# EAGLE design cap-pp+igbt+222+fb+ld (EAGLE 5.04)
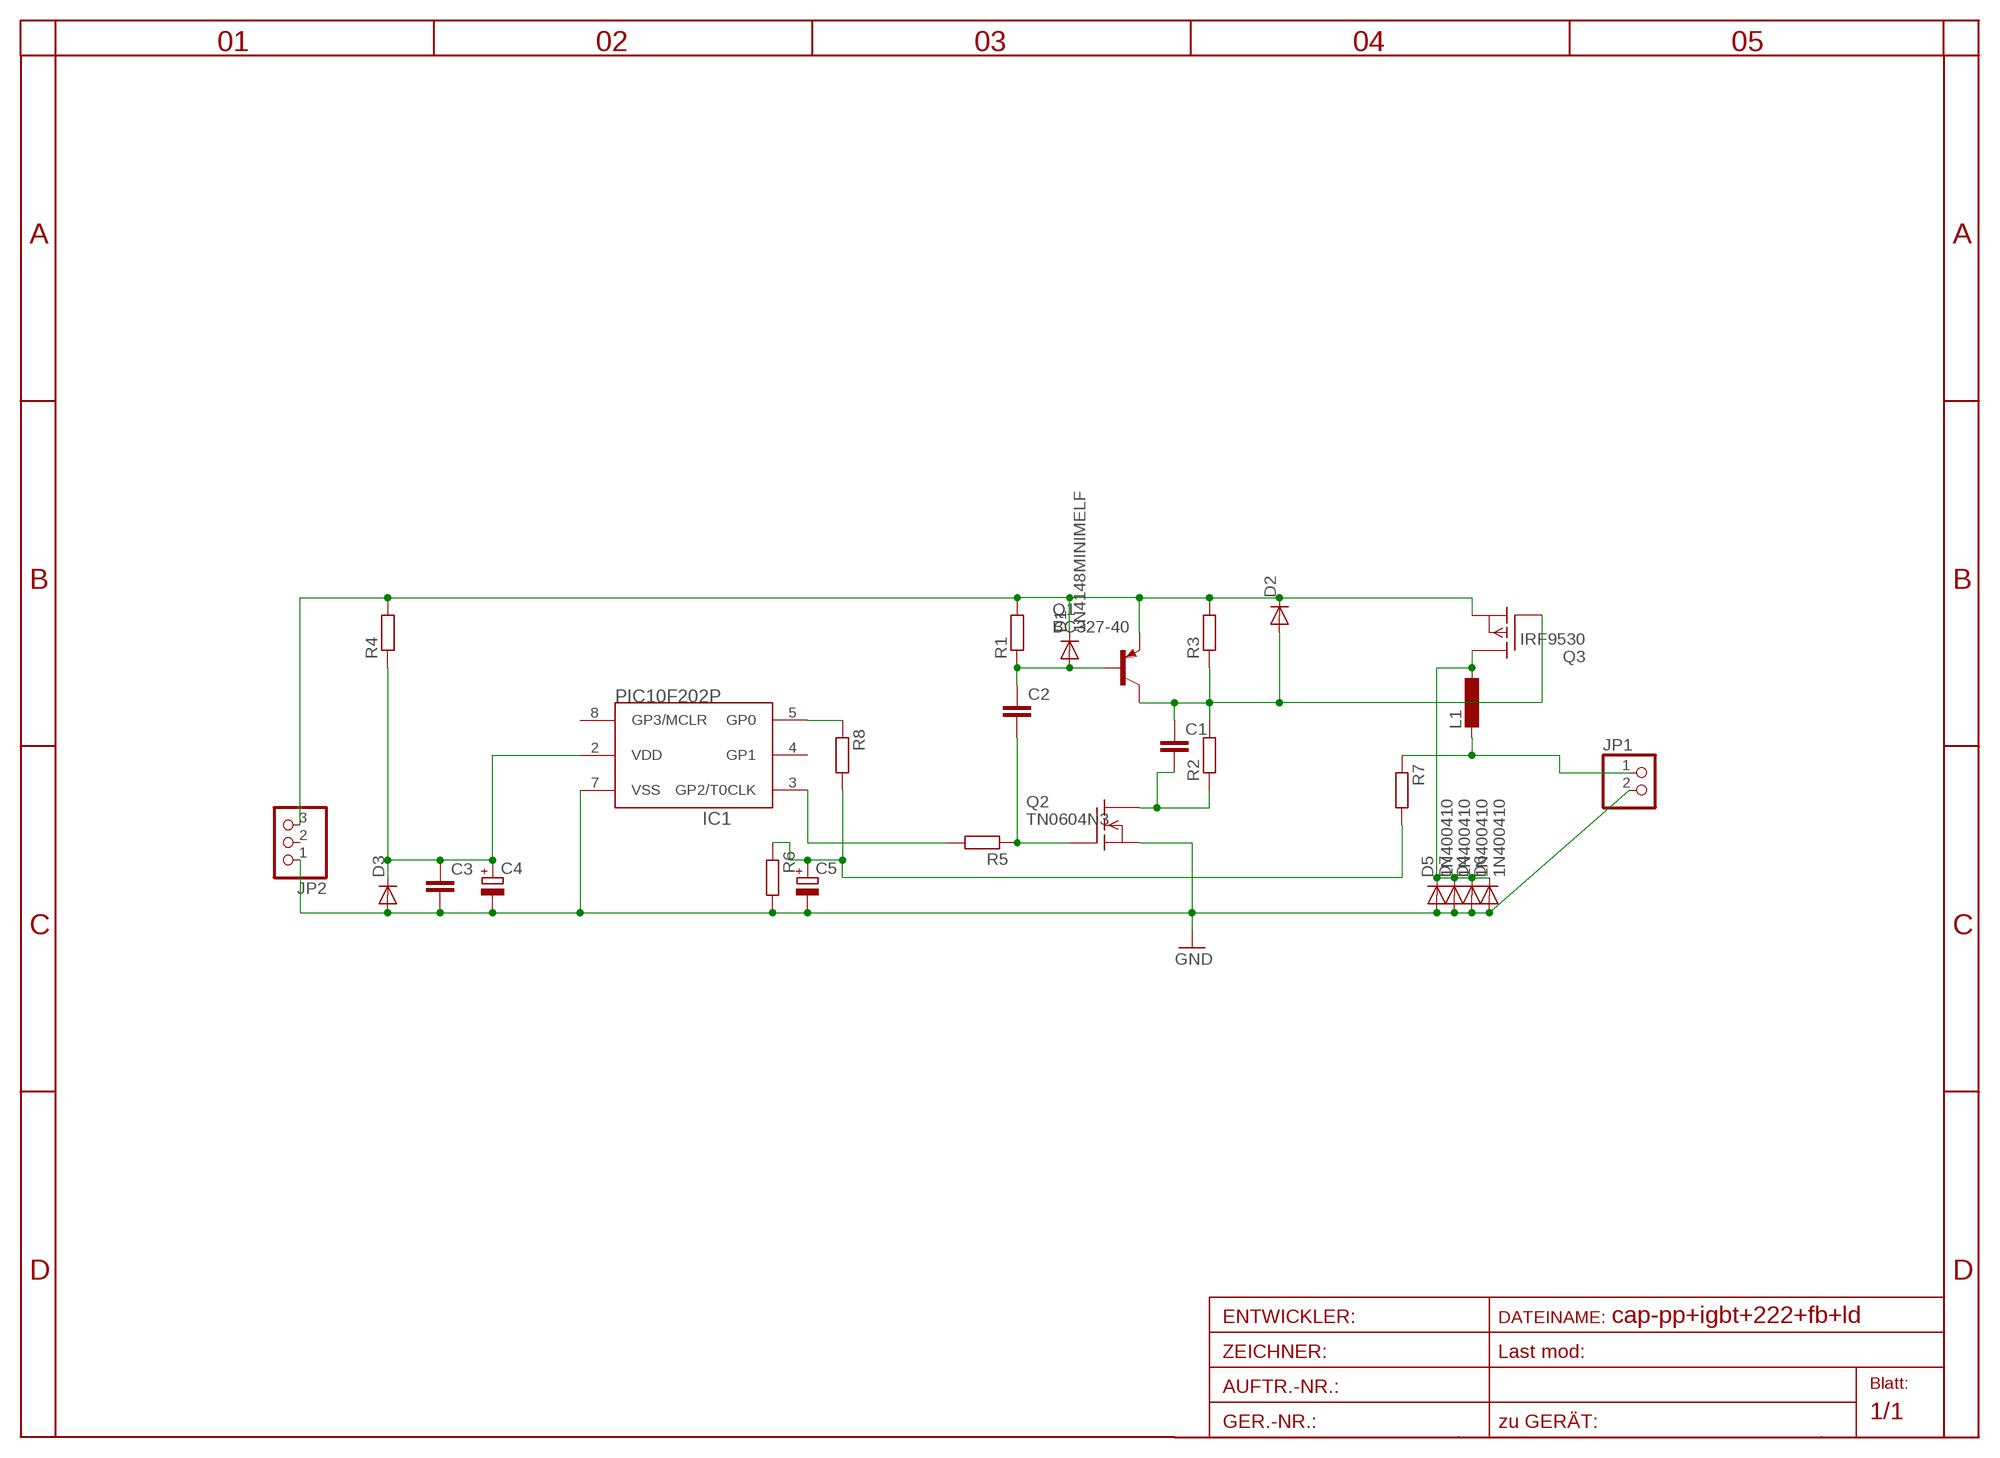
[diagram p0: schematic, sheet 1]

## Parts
C1  C-EU025_050-025X075  [C025_050-025X075]
C2  C-EU025_050-025X075  [C025_050-025X075]
C3  C-EU025_050-025X075  [C025_050-025X075]
C4  CPOL-EU5-13  [2,5-5-FLAT]
C5  CPOL-EU5-13  [2,5-5-FLAT]
D1  1N4148MINIMELF  [MINIMELF]
D2  DIODE-D-5  [D-5]
D3  DIODE-D-2.5  [D-2.5]
D4  1N400410  [DO41-10]
D5  1N400410  [DO41-10]
D6  1N400410  [DO41-10]
D7  1N400410  [DO41-10]
IC1  PIC10F202P  [DIL8]
JP1  PINHD-1X2  [1X02]
JP2  PINHD-1X3  [1X03]
L1  L-EU0204/7  [0204/7]
Q1  BC327-40  [TO92-EBC]
Q2  TN0604N3  [TO-92]
Q3  IRF9530  [TO220]
R1  R-EU_0204/2V  [0204V]
R2  R-EU_0204/2V  [0204V]
R3  R-EU_0204/2V  [0204V]
R4  R-EU_0204/2V  [0204V]
R5  R-EU_0204/2V  [0204V]
R6  R-EU_0204/2V  [0204V]
R7  R-EU_0204/2V  [0204V]
R8  R-EU_0204/2V  [0204V]

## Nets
BB: C2.2 Q2.2(G) R5.1
DRAIN: D4.C D5.C D6.C D7.C L1.1 Q3.2(D)
GND: C3.2 C4.- C5.- D3.A D4.A D5.A D6.A D7.A IC1.7(VSS) JP1.2 JP2.1 Q2.1(S) R6.2
MPOINT: C5.+ R6.1 R7.2 R8.2
N$1: C1.2 Q2.3(D) R2.1
N$3: IC1.3(GP2/T0CLK) R5.2
N$4: C3.1 C4.+ D3.C IC1.2(VDD) R4.1
N$5: IC1.5(GP0) R8.1
OUT: C1.1 D2.A Q1.C Q3.1(G) R2.2 R3.1
OUT+: JP1.1 L1.2 R7.1
TB: C2.1 D1.A Q1.B R1.1
V+: D1.C D2.C JP2.3 Q1.E Q3.3(S) R1.2 R3.2 R4.2
Unconnected: IC1.4(GP1) IC1.8(GP3/MCLR) JP2.2

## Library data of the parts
C1-C3 = rcl-2:C-EU: CAPACITOR, European symbol
C4 C5 = rcl-2:CPOL-EU: POLARIZED CAPACITOR, European symbol
D1 = diode-1:1N4148: DIODE
D2 D3 = diode-1:DIODE-: DIODE
D4-D7 = diode-1:1N4004: DIODE
IC1 = microchip-5:PIC10F20*: uPC nW 0,25/0,5k Program Flash memory
JP1 = pinhead:PINHD-1X2: PIN HEADER
JP2 = pinhead:PINHD-1X3: PIN HEADER
L1 = rcl-2:L-EU: INDUCTOR, European symbol
Q1 = transistor-pnp:BC327*: PNP Transistror
Q2 = transistor-fet:TN0604N3: N-Channel Enhancement MOSFET 40V; 4A; 0,75Ohm
Q3 = transistor-fet:IRF9530: P-Channel Enhancement MOSFET (HEXFET); -100V; -12A; 0,3Ohm
R1-R8 = rcl-2:R-EU_: RESISTOR, European symbol

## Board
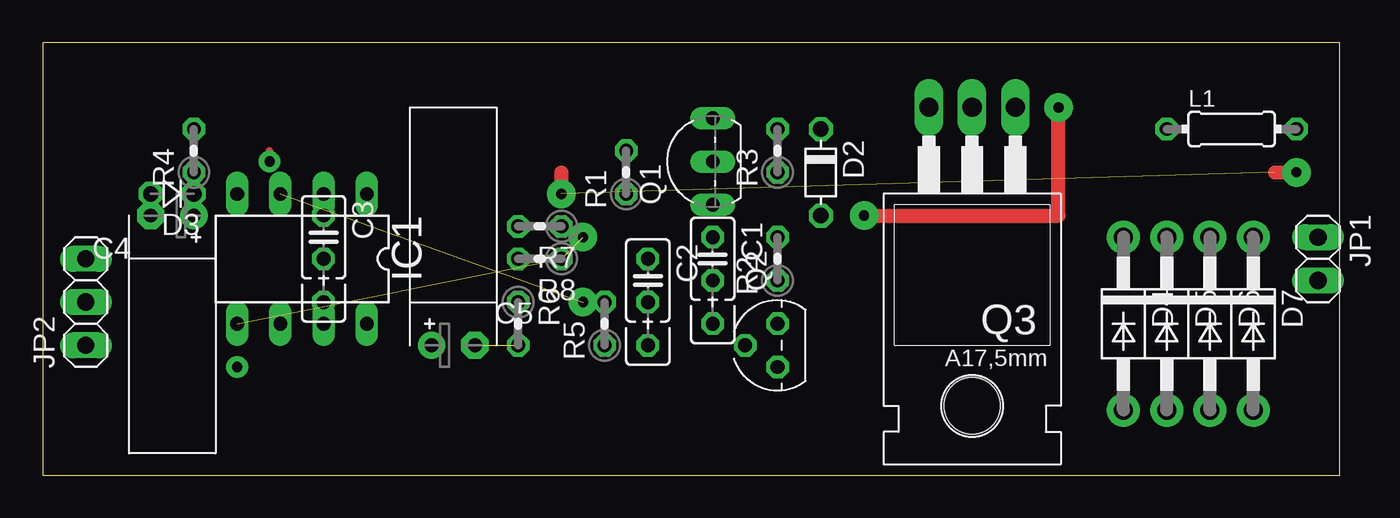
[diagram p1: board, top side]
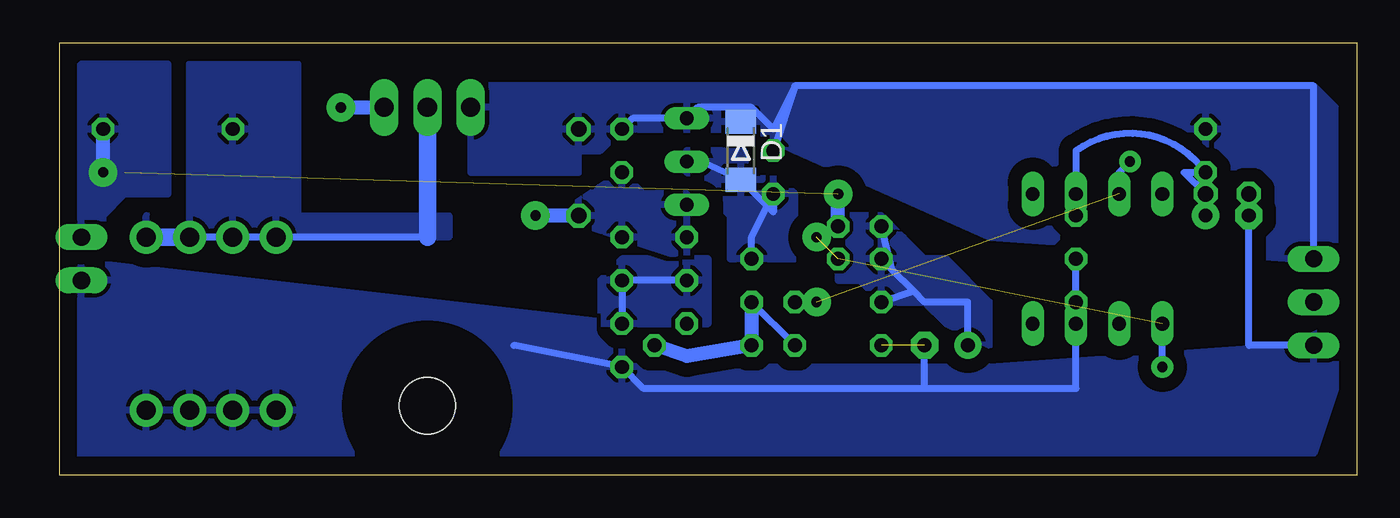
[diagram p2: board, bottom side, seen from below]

Size 76.2 x 25.4 mm. Coordinates in mm from the lower left corner, seen from the top.
Outline: 0,0 76.2,0 76.2,25.4 0,25.4 0,0
Copper layers (1*16): Top 0.035mm / dielectric 1.5mm / Bottom 0.035mm
Design rules "default": minimum track width 10mil, minimum drill 24mil, track to track 8mil, track to pad 8mil, pad to pad 8mil, via to via 8mil, smd to smd 8mil, copper to edge 40mil, drill to drill 8mil, minimum pad ring 10mil, minimum via ring 8mil, stop-mask expansion 4mil, vias tented up to drill 0mil, thermal gap 10mil

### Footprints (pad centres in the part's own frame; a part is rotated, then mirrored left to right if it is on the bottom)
C025_050-025X075 = drill 0.813 octagon: 1 -1.27,0; 2 1.27,0; 3 3.81,0
2,5-5-FLAT = drill 0.813 pad 1.6 round: + -1.27,0 | drill 0.813 pad 1.6 octagon: - 1.27,0
MINIMELF = smd 1.4 x 1.8: A 1.7,0; C -1.7,0
D-5 = drill 0.9 octagon: A 2.54,0; C -2.54,0
D-2.5 = drill 0.9 octagon: A 1.27,0; C -1.27,0
DO41-10 = drill 1.118 pad 1.93 round: A 5.08,0; C -5.08,0
DIL8 = drill 0.813 long: 1 -3.81,-3.81; 2 -1.27,-3.81; 3 1.27,-3.81; 4 3.81,-3.81; 5 3.81,3.81; 6 1.27,3.81; 7 -1.27,3.81; 8 -3.81,3.81
1X02 = drill 1.016 long: 1 -1.27,0; 2 1.27,0
1X03 = drill 1.016 long: 1 -2.54,0; 2 0,0; 3 2.54,0
0204/7 = drill 0.813 octagon: 1 -3.81,0; 2 3.81,0
TO92-EBC = drill 0.813 long: B 0,-1.27; C -2.54,-1.27; E 2.54,-1.27
TO-92 = drill 0.813 octagon: 1 -1.27,0; 2 0,1.905; 3 1.27,0
TO220 = drill 1.118 long: 1 -2.54,-6.35; 2 0,-6.35; 3 2.54,-6.35 | hole 3.302: 0,11.176
0204V = drill 0.813 octagon: 1 -1.27,0; 2 1.27,0

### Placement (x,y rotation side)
C1  39.37,12.7 270 top
C2  35.56,11.43 270 top
C3  16.51,13.97 270 top
C4  7.62,15.24 180 top
C5  24.13,7.62 0 top
D1  36.2,19.05 270 bottom
D2  45.72,17.78 270 top
D3  7.62,16.51 180 top
D4  63.5,8.89 270 top
D5  66.04,8.89 270 top
D6  68.58,8.89 270 top
D7  71.12,8.89 270 top
IC1  15.24,12.7 180 top
JP1  74.93,12.7 270 top
JP2  2.54,10.16 90 top
L1  69.85,20.32 0 top
Q1  38.1,18.41 90 top
Q2  43.18,7.62 90 top
Q3  54.61,15.24 180 top
R1  34.29,17.78 90 top
R2  43.18,12.7 90 top
R3  43.18,19.05 90 top
R4  8.89,19.05 90 top
R5  33.02,8.89 90 top
R6  27.94,8.89 270 top
R7  29.21,14.61 180 top
R8  29.21,12.7 180 top

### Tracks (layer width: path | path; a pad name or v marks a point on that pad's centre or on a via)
BB
  Bottom 0.406: R5.1 C2.2
  Bottom 0.813: Q2.2 39.37,6.99 35.56,7.62 C2.2
DRAIN
  Bottom 0.406: Q3.2 54.61,22.86 | 54.61,13.97 D4.C D5.C D6.C
  Bottom 1.016: 54.61,13.97 Q3.2 | D6.C D7.C
  pour Bottom (isolate 0.61): 68.58,24.13 62.23,24.13 62.23,15.24 55.88,15.24 53.34,15.24 53.34,13.97 71.12,13.97 71.12,15.24 68.58,15.24
GND  (1 unrouted)
  Bottom 0.406: 49.53,7.62 Q2.1 41.91,5.08 25.4,5.08 | D3.A C4.- 6.35,7.62 JP2.1 | C3.2 IC1.7 16.51,5.08 25.4,5.08 | 25.4,5.08 C5.-
  pour Bottom (isolate 0.813): 1.27,8.89 1.27,5.08 2.54,1.27 76.2,1.27 76.2,12.7 43.18,8.89 41.91,6.35 21.59,6.35 3.81,7.62
MPOINT
  Bottom 0.406: C5.+ 22.86,10.16 25.4,10.16 26.04,10.79 | 26.04,10.79 27.3,12.06 | 27.3,12.06 R7.2 | 26.04,10.79 R6.1 | 27.3,12.06 R8.2
  pour Bottom: 21.59,7.62 21.59,10.16 24.13,12.7 25.4,12.7 26.67,13.97 27.94,15.24 30.48,15.24 30.48,11.43 29.21,11.43 27.94,10.16 25.4,10.16 24.13,8.89
N$1
  Bottom 0.406: C1.2 R2.1 Q2.3
  pour Bottom (isolate 0.254, rank 3): 38.1,12.7 43.18,12.7 44.45,11.43 44.45,8.89 38.1,8.89
N$3  (via drill 0.6 pad 1.27, 0.6 pad 1.68)  (1 unrouted)
  Top 0.406: v13.34,18.41 13.34,19.05
  Bottom 0.406: IC1.3 13.97,17.78 v13.34,18.41
  Bottom 0.813: v31.75,10.16 R5.2
N$4
  Bottom 0.406: C4.+ D3.C 10.16,17.78 R4.1 arc-90 16.51,19.05 IC1.2 C3.1
N$5  (via drill 0.6 pad 1.27, 0.6 pad 1.68)  (2 unrouted)
  Bottom 0.406: v11.43,6.35 IC1.5
  other vias: 31.75,13.97
OUT  (via drill 0.6 pad 1.68)
  Top 0.813: v59.69,21.59 59.69,15.24 v48.26,15.24
  Bottom 0.813: v59.69,21.59 Q3.1 | D2.A v48.26,15.24
  pour Bottom (isolate 0.813, rank 2): 39.37,16.51 41.91,16.51 43.18,17.78 46.99,15.24 39.37,12.7
OUT+  (via drill 0.6 pad 1.68)  (1 unrouted)
  Top 0.813: v30.48,16.51 30.48,17.78 | 72.39,17.78 v73.66,17.78
  Bottom 0.813: R7.1 v30.48,16.51 | v73.66,17.78 L1.2
  pour Bottom (isolate 0.61): 69.85,24.13 74.93,24.13 76.2,22.86 76.2,13.97 73.66,13.97 73.66,15.24 72.39,16.51 69.85,16.51
TB
  Bottom 0.406: C2.1 35.56,13.97 R1.1 34.29,15.45 D1.A 38.94,18.62 39.16,18.62 Q1.B
  pour Bottom (isolate 0.813, rank 3): 36.83,12.7 33.02,12.7 33.02,16.51 35.56,19.05 39.37,19.05 39.37,17.78 36.83,15.24
V+
  Bottom 0.406: JP2.3 2.54,22.86 33.02,22.86 | 33.02,22.86 34.29,20.32 35.56,21.59 36.83,21.59 | 36.83,21.59 38.73,21.59 Q1.E 42.55,20.95 R3.2 | D1.C 36.2,20.95 36.83,21.59 | 33.02,22.86 R1.2
  pour Bottom (isolate 0.813): 1.27,12.7 1.27,21.59 2.54,22.86 52.07,22.86 52.07,17.78 45.72,17.78 45.72,19.05 44.45,19.05 43.18,20.32 35.56,20.32 33.02,19.05 21.59,13.97 3.81,12.7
